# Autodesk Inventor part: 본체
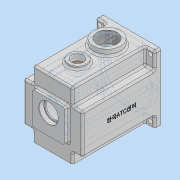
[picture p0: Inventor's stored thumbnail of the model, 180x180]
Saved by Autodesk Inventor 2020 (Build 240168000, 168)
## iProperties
Created: 2022-01
Part Number: 본체
Material: 일반
Document SubType Name: Modeling
Designer: user
Density: 1 g/cm^3
Appearance: 기본값
Mass: 555.176 g
Surface Area: 1187.47 cm^2
Volume: 555.176 cm^3
Author: user
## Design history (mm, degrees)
sketch "스케치1"
  geometry: L1 (-49, -50)-(49, -50); L2 (49, -50)-(49, 60); L3 (49, 60)-(-49, 60); L4 (-49, 60)-(-49, -50); 1 further point
  constraints: 8 end point, 2 parallel, 1 horizontal, 1 perpendicular
  dimensions: "d0" = 98 distance of L3.end L2.end; "d52" = 50 distance from line of L1 point (0, 0); "d53" = 110 distance between parallel lines of L1 L3
extrude "돌출1" new body sketch "스케치1" distance "d2" = 130; taper "d3" = 0 deg
sketch "스케치2"
  geometry: L1 (-49, 60)-(-49, -50) reference; L2 (-49, -50)-(49, -50) reference; L3 (49, -50)-(49, 60) reference; L4 (49, 60)-(-49, 60) reference; L5 (-49, 60)-(-33, 60); L6 (-33, 60)-(-33, 33); L7 (-33, 33)-(-49, 33); L8 (-49, 33)-(-49, 60); L9 (49, -50)-(49, 60) reference; L10 (49, 60)-(33, 60); L11 (33, 60)-(33, 33); L12 (33, 33)-(49, 33); L13 (49, 33)-(49, 60); L14 (-49, 60)-(-49, -50) reference; L15 (-49, -50)-(-33, -50); L16 (-33, -50)-(-33, -33); L17 (-33, -33)-(-49, -33); L18 (-49, -33)-(-49, -50); L19 (-49, -50)-(49, -50) reference; L20 (49, -50)-(33, -50); L21 (33, -50)-(33, -33); L22 (33, -33)-(49, -33); L23 (49, -33)-(49, -50); 9 further points
  constraints: 32 end point, 8 parallel, 4 horizontal, 4 perpendicular
  dimensions: "d6" = 16 distance of L6.end L7.end; "d7" = 27 distance of L5.end L6.end; "d8" = 16 distance of L12.end L11.end; "d9" = 27 distance of L11.end L10.end; "d10" = 16 distance of L17.end L16.end; "d11" = 17 distance of L16.end L15.end; "d12" = 16 distance of L21.end L22.end; "d13" = 17 distance of L20.end L21.end
extrude "돌출2" cut sketch "스케치2" distance "d14" = 120; taper "d15" = 0 deg
sketch "스케치3"
  geometry: L1 (-27, -22)-(27, -22); L2 (27, -22)-(27, 32); L3 (27, 32)-(-27, 32); L4 (-27, 32)-(-27, -22); L5 (33, 60)-(-33, 60) reference; L6 (-27, 32)-(27, -22); L7 (27, 32)-(-27, -22)
  constraints: 12 end point, 2 parallel, 1 horizontal, 1 perpendicular
  dimensions: "d16" = 54 distance of L3.end L2.end; "d17" = 54 distance of L2.end L1.end; "d78" = 28 distance between parallel lines of L3 L5
extrude "돌출3" join sketch "스케치3" distance "d18" = 7; taper "d19" = 0 deg
sketch "스케치6"
  geometry: L1 (-23, 50)-(23, 50); L2 (23, 50)-(23, 25.666); L3 (23, 25.666)-(-23, 25.666); L4 (-23, 25.666)-(-23, 50); L5 (-23, 50)-(23, 25.666); L6 (23, 50)-(-23, 25.666); C1 r 42 at (0, 0); 5 further points
  constraints: 12 end point, 3 midpoint, 2 parallel, 1 centre point, 1 coincident, 1 horizontal, 1 perpendicular, 1 vertical alignment
  dimensions: "d24" = 84 diameter of C1; "d25" = 46 distance of L2.end L3.end; "d26" = 50 distance from line of L1 point (0, 0)
extrude "돌출5" cut sketch "스케치6" distance "d27" = 114; taper "d28" = 0 deg
sketch "스케치14"
  geometry: L1 (-23, 35.143)-(-23, 50) reference; L2 (23, 50)-(23, 35.143) reference; L3 (-23, 50)-(23, 50) reference; L4 (-26, 36.729)-(-26, 53); L5 (-26, 53)-(26, 53); L6 (26, 53)-(26, 36.729); A1 r 42 centre (0, 0) between (-23, 35.143) and (23, 35.143) reference; A2 r 45 centre (0, 0) between (-26, 36.729) and (26, 36.729); 1 further point
  constraints: 6 end point, 2 point on circle, 1 centre point, 3 other
  dimensions: "d51" = 3 radial gap between concentric circles of A1 A2
  node "투영된 루프3"
sketch "스케치15"
  geometry: 1 further point
extrude "돌출13" cut sketch "스케치14" distance "d54" = 9; taper "d55" = 0 deg
sketch "스케치17"
  geometry: C1 r 21 at (0, 11); C2 r 15 at (0, -20); 3 further points
  constraints: 2 centre point
  dimensions: "d60" = 42 diameter of C1; "d61" = 30 diameter of C2; "d62" = 20 distance of C2.centre point (0, 0); "d63" = 11 distance of point (0, 0) C1.centre
extrude "돌출14" join sketch "스케치17" distance "d64" = 7; taper "d65" = 0 deg
node "작업 평면1"
sketch "스케치19"
  geometry: L1 (98, 0)-(0, 0) reference; C1 r 22.5 at (49, -40); 1 further point
  constraints: 1 centre point
  dimensions: "d70" = 45 diameter of C1; "d71" = 40 distance of C1.centre point (49, 0)
extrude "돌출16" join sketch "스케치19" stored distance "d72" = 10; taper "d73" = 0 deg
sketch "스케치22"
  geometry: C1 r 11 at (0, -20); A1 r 15 centre (0, -20) between (-8.978, -7.984) and (8.978, -7.984) reference; A2 r 21 centre (0, 11) between (8.978, -7.984) and (-8.978, -7.984) reference; 1 further point
  constraints: 1 centre point, 1 coincident
  dimensions: "d84" = 22 diameter of C1
  node "투영된 루프6"
node "작업 평면2"
sketch "스케치23"
  geometry: C1 r 22.5 at (49, -40) reference; C2 r 15 at (49, -89); 1 further point
  constraints: 1 centre point
  dimensions: "d80" = 30 diameter of C2; "d81" = 49 distance of C1.centre C2.centre
extrude "돌출18" join sketch "스케치23" stored distance "d82" = 7; taper "d83" = 0 deg
sketch "스케치24"
  geometry: L1 (-26, 36.729)-(-26, 53) reference; L2 (-26, 53)-(26, 53) reference; L3 (26, 53)-(26, 36.729) reference; L4 (49, 60)-(49, -50) reference; L5 (-49, 60)-(49, 60) reference; L6 (-49, -50)-(-49, 60) reference; L7 (49, -50)-(-49, -50) reference; L8 (42, -43)-(-42, -43); L9 (-42, -43)-(-42, 53); L10 (-42, 53)-(42, 53); L11 (42, 53)-(42, -43); C1 r 3.5 at (-42, 53); C2 r 3.5 at (42, 53); C3 r 3.5 at (42, -43); C4 r 3.5 at (-42, -43); A1 r 45 centre (0, 0) between (-26, 36.729) and (26, 36.729) reference; 1 further point
  constraints: 8 end point, 4 centre point, 4 coincident, 2 parallel, 1 horizontal, 1 perpendicular
  dimensions: "d85" = 84 distance of L9.end L10.end; "d86" = 96 distance of L8.end L9.end; "d87" = 7 distance between parallel lines of L5 L10; "d88" = 7 distance between parallel lines of L9 L6; "d89" = 7 diameter of C1; "d90" = 7 diameter of C2; "d91" = 7 diameter of C3; "d92" = 7 diameter of C4
extrude "돌출19" cut sketch "스케치24" extent not by distance; stored distance "d93" = 0; taper "d94" = 0 deg
sketch "스케치25"
  geometry: C1 r 22.5 at (0, 0) reference; 2 further points
  constraints: 1 coincident
hole "구멍1" sketch "스케치25" at (0, 0) diameter "d95" = 33.376; stored, may be unused: countersink angle "d99" = 90 deg, drill point angle "d101" = 118 deg; dims "d96" = 70, "d97" = 4, "d98" = 2, "d100" = 77.3
sketch "스케치26"
  geometry: C1 r 15 at (0, 0) reference; C2 r 10 at (0, 0); 1 further point
  constraints: 1 centre point, 1 coincident
  dimensions: "d102" = 20 diameter of C2
extrude "돌출20" cut sketch "스케치26" distance "d103" = 53; taper "d104" = 0 deg
extrude "돌출21" cut sketch "스케치22" distance "d105" = 7; taper "d106" = 0 deg
sketch "스케치27"
  geometry: C1 r 11 at (0, 0) reference; C2 r 9.5 at (0, 0); 1 further point
  constraints: 1 centre point, 1 coincident
  dimensions: "d107" = 19 diameter of C2
extrude "돌출22" cut sketch "스케치27" distance "d108" = 3; taper "d109" = 0 deg
sketch "스케치28"
  geometry: C1 r 11 at (0, -20) reference; C2 r 17.5 at (0, 11); A1 r 15 centre (0, -20) between (-8.978, -7.984) and (8.978, -7.984) reference; A2 r 21 centre (0, 11) between (8.978, -7.984) and (-8.978, -7.984) reference; 1 further point
  constraints: 1 centre point, 1 coincident
  dimensions: "d110" = 35 diameter of C2
extrude "돌출23" cut sketch "스케치28" distance "d111" = 10; taper "d112" = 0 deg
sketch "스케치33"
  geometry: C1 r 17.5 at (0, 0) reference; C2 r 17.5 at (0, 0) reference; C3 r 17.5 at (0, 0); 1 further point
  constraints: 1 centre point, 1 coincident
  dimensions: "d122" = 35 diameter of C3
extrude "돌출27" cut sketch "스케치33" distance "d123" = 10; taper "d124" = 0 deg
sketch "스케치34"
  geometry: C1 r 17.5 at (0, 0) reference; C2 r 14 at (0, 0); 1 further point
  constraints: 1 centre point, 1 coincident
  dimensions: "d125" = 28 diameter of C2
extrude "돌출28" cut sketch "스케치34" extent not by distance; stored distance "d126" = 20; taper "d127" = 0 deg
sketch "스케치35"
  geometry: C1 r 14 at (0, 11) reference; C2 r 16 at (0, 11); 1 further point
  constraints: 1 centre point, 1 coincident
  dimensions: "d128" = 32 diameter of C2
extrude "돌출29" cut sketch "스케치35" distance "d129" = 0.8; taper "d130" = 0 deg
node "작업 평면3"
sketch "스케치36"
  geometry: C1 r 16 at (0, 11) reference; C2 r 16 at (0, 11); 1 further point
  constraints: 1 centre point, 1 coincident
  dimensions: "d132" = 32 diameter of C2
extrude "돌출30" cut sketch "스케치36" distance "d133" = 7.5; taper "d134" = 0 deg
sketch "스케치37" dims "d135" = 72
  geometry: L1 (-36, 4)-(-41.809, 4); L2 (-36, -4)-(-41.809, -4); A1 r 4 centre (-36, 0) between (-36, 4) and (-36, -4); A2 r 42 centre (0, 0) between (-23, 35.143) and (23, 35.143) reference; 2 further points
  constraints: 4 end point, 4 point on circle, 2 horizontal alignment, 2 tangent, 1 centre point, 1 coincident, 1 horizontal, 1 parallel, 2 other
  dimensions: "d137" = 8 diameter of A1
fillet "모깎기1" dims "d138" = 3
fillet "모깎기2" dims "d139" = 3
fillet "모깎기3" dims "d140" = 3
fillet "모깎기4" dims "d141" = 0.3
chamfer "모따기1" distance "d142" = 1; stored, may be unused: second distance "d143" = 2, angle "d144" = 30 deg
chamfer "모따기2" distance "d145" = 0.8; stored, may be unused: second distance "d146" = 2, angle "d147" = 30 deg
fillet "모깎기5" dims "d148" = 3
fillet "모깎기6" dims "d149" = 3
fillet "모깎기7" dims "d150" = 3
fillet "모깎기8" dims "d151" = 3
fillet "모깎기9" dims "d152" = 3
sketch "스케치38"
  geometry: L1 (-130, 107)-(-130, 86) reference; L2 (-13, 83)-(-127, 83) reference; 2 further points
  constraints: 1 other
  dimensions: "d153" = 65 distance from line of L1 point (-65, 50); "d154" = 33 distance from line of L2 point (-65, 50)
feature "엠보싱1" sketch "스케치38" dims "d155" = 0.5, "d156" = 0
extrude "돌출31" join sketch "스케치37" stored distance "d157" = 0.8; taper "d158" = 0 deg
sketch "스케치39"
  geometry: L1 (-36, 4)-(-41.809, 4) reference; L2 (-41.809, -4)-(-36, -4) reference; L3 (36, 4)-(41.809, 4) reference; L4 (41.809, -4)-(36, -4) reference; A1 r 42 centre (0, 0) between (-41.809, 4) and (-41.809, -4) reference; A2 r 4 centre (-36, 0) between (-36, -4) and (-36, 4) reference; A3 r 4 centre (36, 0) between (36, 4) and (36, -4) reference; A4 r 42 centre (0, 0) between (41.809, -4) and (41.809, 4) reference; 1 further point
hole "구멍2" sketch "스케치39" at (-36, 0), (36, 0) diameter "d159" = 3.242; stored, may be unused: countersink angle "d163" = 90 deg, drill point angle "d165" = 118 deg; dims "d160" = 7, "d161" = 4, "d162" = 2, "d164" = 9
fillet "모깎기10" dims "d166" = 6
fillet "모깎기11" dims "d167" = 3
fillet "모깎기12" dims "d168" = 6
fillet "모깎기13" dims "d169" = 3
fillet "모깎기14" dims "d170" = 3
fillet "모깎기15" dims "d171" = 3
node "작업 평면4"
sketch "스케치40"
  geometry: C1 r 10 at (0, 0) reference; C2 r 15 at (0, 0) reference; C3 r 15 at (0, 0); 1 further point
  constraints: 1 centre point, 1 coincident
  dimensions: "d173" = 30 diameter of C3
extrude "돌출32" cut sketch "스케치40" distance "d174" = 5; taper "d175" = 0 deg
chamfer "모따기3" distance "d176" = 1; stored, may be unused: second distance "d177" = 2, angle "d178" = 30 deg
node "솔리드1"
mirror "미러1"
node "투영된 루프1"
node "투영된 루프7"
node "투영된 루프8"
node "투영된 루프9"
node "투영된 루프14"
node "투영된 루프15"
node "투영된 루프16"
node "투영된 루프17"
node "투영된 루프18"
feature "A9D066F2-1C7D-4E18-AEED-F7BC21143FA4" dims "d95" = 33.376, "d96" = 70, "d97" = 4, "d98" = 2, "d99" = 90 deg, "d100" = 77.3, "d101" = 118 deg
other parameters: "d79" = 5, "d131" = -0.8
